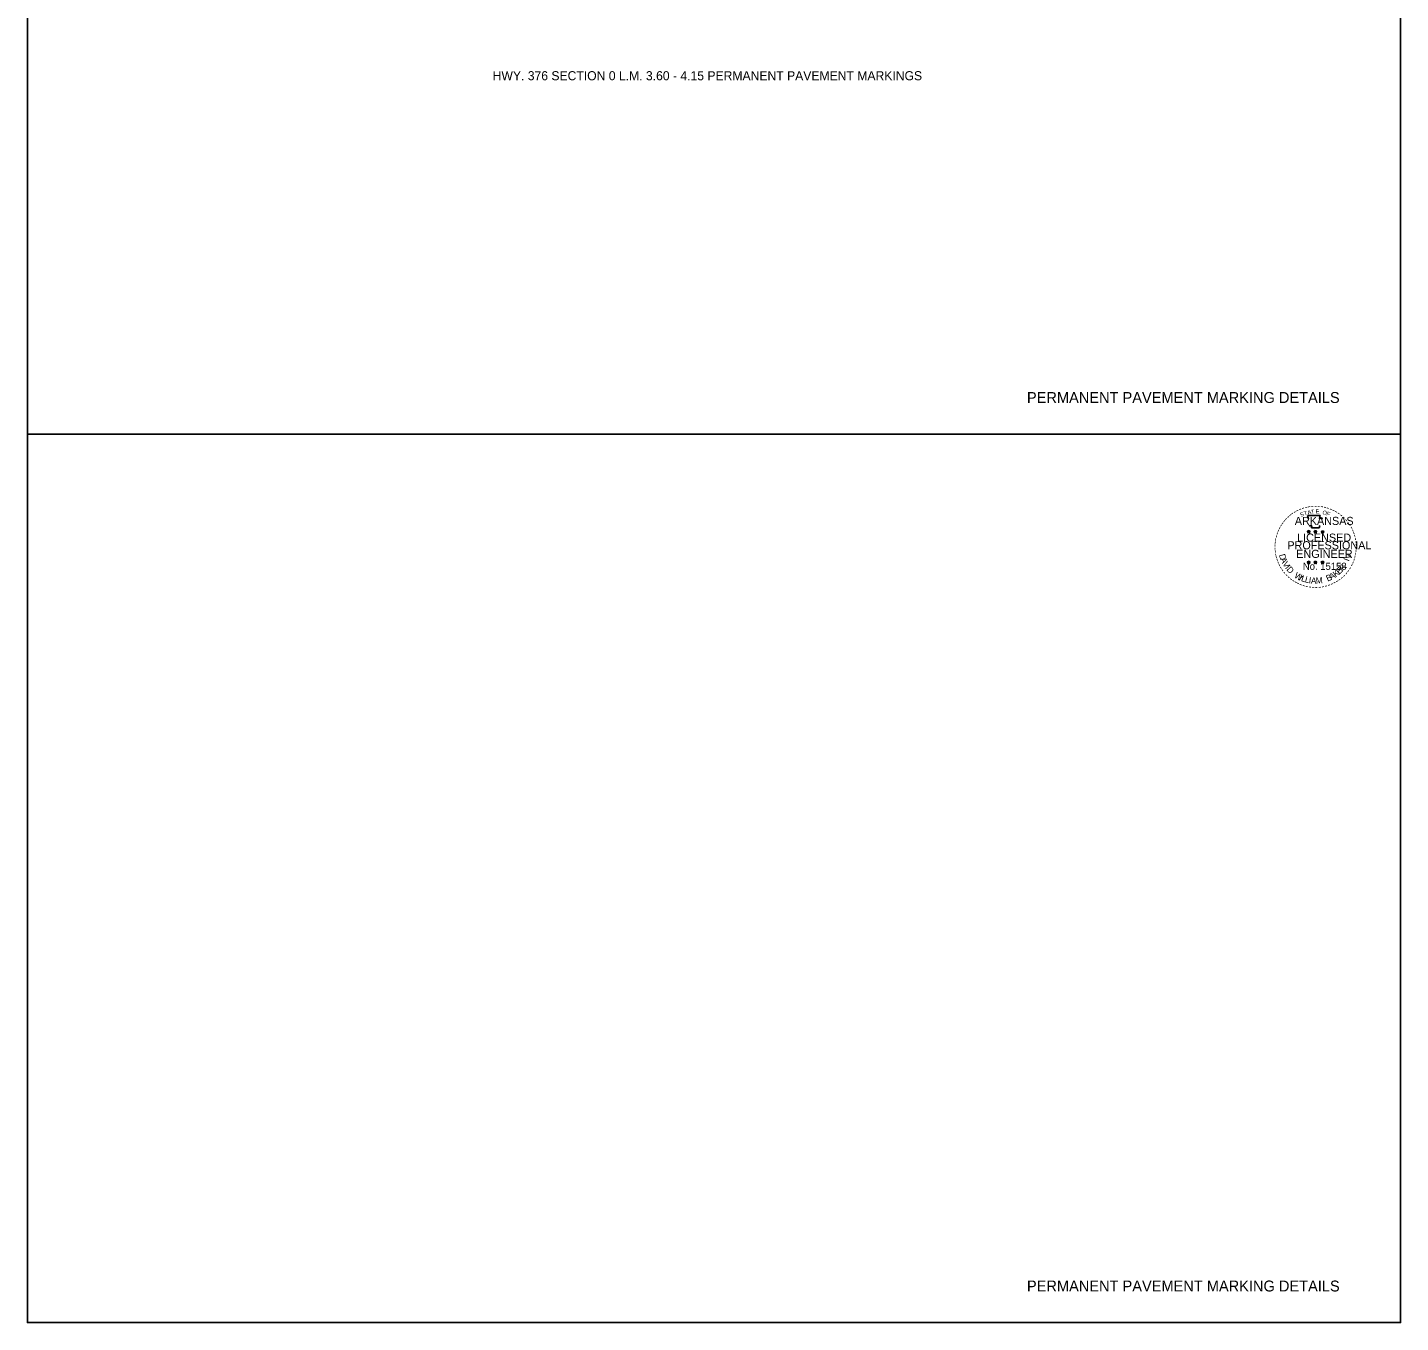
# Model space of a CAD drawing. Extents: x 1372926 to 1373096, y 381240 to 381790.
# Drawn here: x 1372926 to 1373096, y 381240.2 to 381400.5 of the extents above; entities that cross this region are included whole.
import ezdxf

# ---------------------------------------------------------------- set-up
doc = ezdxf.new("R2010")
doc.units = 0
for name, color, linetype in [('Default', 7, 'Continuous'), ('DSN_DRFT_Junk-No-Plot', 7, 'Continuous'), ('R_Border Notes', 7, 'Continuous'), ('R_Draft', 7, 'Continuous'), ('SHET_Border-Text', 7, 'Continuous')]:
    doc.layers.add(name, color=color, linetype=linetype)

msp = doc.modelspace()

# ---------------------------------------------------------------- linework, layer by layer
at = {"layer": 'Default'}
for points in [[(1372925.97, 381460.17), (1372925.97, 381350.17), (1373095.97, 381350.17), (1373095.97, 381460.17)], [(1372925.97, 381350.17), (1372925.97, 381240.17), (1373095.97, 381240.17), (1373095.97, 381350.17)]]:
    msp.add_lwpolyline(points, close=True, dxfattribs=at)
at = {"layer": 'DSN_DRFT_Junk-No-Plot'}
for points in [[(1372925.97, 381460.17), (1373095.97, 381460.17), (1373095.97, 381350.17), (1372925.97, 381350.17)], [(1372925.97, 381460.17), (1372925.97, 381350.17), (1373095.97, 381350.17), (1373095.97, 381460.17)], [(1372925.97, 381350.17), (1373095.97, 381350.17), (1373095.97, 381240.17), (1372925.97, 381240.17)], [(1372925.97, 381350.17), (1372925.97, 381240.17), (1373095.97, 381240.17), (1373095.97, 381350.17)]]:
    msp.add_lwpolyline(points, close=True, dxfattribs=at)
at = {"layer": 'SHET_Border-Text'}
for p, q in [((1373084.43, 381338.13), (1373084.6, 381338.07)), ((1373084.43, 381338.13), (1373084.56, 381338.11)), ((1373084.43, 381338.13), (1373084.55, 381338.07)), ((1373084.5, 381337.93), (1373084.6, 381338.07)), ((1373084.5, 381337.93), (1373084.56, 381338.05)), ((1373084.5, 381337.93), (1373084.6, 381338.03)), ((1373084.6, 381338.26), (1373084.58, 381338.13)), ((1373084.6, 381338.07), (1373084.6, 381338.26)), ((1373084.6, 381338.26), (1373084.63, 381338.13)), ((1373084.78, 381338.13), (1373084.6, 381338.07)), ((1373084.71, 381337.93), (1373084.6, 381338.07)), ((1373084.71, 381337.93), (1373084.6, 381338.03)), ((1373084.78, 381338.13), (1373084.63, 381338.11)), ((1373084.71, 381337.93), (1373084.64, 381338.07)), ((1373084.78, 381338.13), (1373084.67, 381338.08)), ((1373085.26, 381338.13), (1373085.44, 381338.07)), ((1373085.26, 381338.13), (1373085.39, 381338.11)), ((1373085.26, 381338.13), (1373085.38, 381338.07)), ((1373085.33, 381337.93), (1373085.44, 381338.07)), ((1373085.33, 381337.93), (1373085.39, 381338.05)), ((1373085.33, 381337.93), (1373085.44, 381338.03)), ((1373085.44, 381338.26), (1373085.42, 381338.13)), ((1373085.44, 381338.07), (1373085.44, 381338.26)), ((1373085.44, 381338.26), (1373085.46, 381338.13)), ((1373085.61, 381338.13), (1373085.44, 381338.07)), ((1373085.54, 381337.93), (1373085.44, 381338.07)), ((1373085.54, 381337.93), (1373085.44, 381338.03)), ((1373085.61, 381338.13), (1373085.47, 381338.11)), ((1373085.54, 381337.93), (1373085.48, 381338.07)), ((1373085.61, 381338.13), (1373085.51, 381338.08)), ((1373086.15, 381338.12), (1373086.32, 381338.07)), ((1373086.15, 381338.12), (1373086.27, 381338.1)), ((1373086.15, 381338.12), (1373086.26, 381338.06)), ((1373086.21, 381337.92), (1373086.32, 381338.07)), ((1373086.21, 381337.92), (1373086.28, 381338.04)), ((1373086.21, 381337.92), (1373086.32, 381338.03)), ((1373086.32, 381338.25), (1373086.3, 381338.12)), ((1373086.32, 381338.07), (1373086.32, 381338.25)), ((1373086.32, 381338.25), (1373086.34, 381338.13)), ((1373086.49, 381338.12), (1373086.32, 381338.07)), ((1373086.43, 381337.92), (1373086.32, 381338.07)), ((1373086.43, 381337.92), (1373086.32, 381338.03)), ((1373086.49, 381338.12), (1373086.35, 381338.1)), ((1373086.43, 381337.92), (1373086.36, 381338.07)), ((1373086.49, 381338.12), (1373086.39, 381338.07)), ((1373084.43, 381334.34), (1373084.6, 381334.29)), ((1373084.43, 381334.34), (1373084.55, 381334.32)), ((1373084.43, 381334.34), (1373084.55, 381334.28)), ((1373084.49, 381334.14), (1373084.6, 381334.29)), ((1373084.49, 381334.14), (1373084.56, 381334.26)), ((1373084.49, 381334.14), (1373084.6, 381334.25)), ((1373084.6, 381334.47), (1373084.58, 381334.34)), ((1373084.6, 381334.29), (1373084.6, 381334.47)), ((1373084.6, 381334.47), (1373084.63, 381334.35)), ((1373084.77, 381334.34), (1373084.6, 381334.29)), ((1373084.71, 381334.14), (1373084.6, 381334.29)), ((1373084.71, 381334.14), (1373084.6, 381334.25)), ((1373084.77, 381334.34), (1373084.63, 381334.32)), ((1373084.71, 381334.14), (1373084.64, 381334.28)), ((1373084.77, 381334.34), (1373084.67, 381334.29)), ((1373085.26, 381334.34), (1373085.44, 381334.29)), ((1373085.26, 381334.34), (1373085.39, 381334.32)), ((1373085.26, 381334.34), (1373085.38, 381334.28)), ((1373085.33, 381334.14), (1373085.44, 381334.29)), ((1373085.33, 381334.14), (1373085.39, 381334.26)), ((1373085.33, 381334.14), (1373085.43, 381334.25)), ((1373085.44, 381334.47), (1373085.42, 381334.34)), ((1373085.54, 381334.14), (1373085.43, 381334.25)), ((1373085.44, 381334.29), (1373085.44, 381334.47)), ((1373085.44, 381334.47), (1373085.46, 381334.35)), ((1373085.61, 381334.34), (1373085.44, 381334.29)), ((1373085.54, 381334.14), (1373085.44, 381334.29)), ((1373085.61, 381334.34), (1373085.47, 381334.32)), ((1373085.54, 381334.14), (1373085.47, 381334.28)), ((1373085.61, 381334.34), (1373085.51, 381334.29)), ((1373086.14, 381334.34), (1373086.32, 381334.28)), ((1373086.14, 381334.34), (1373086.27, 381334.32)), ((1373086.14, 381334.34), (1373086.26, 381334.28)), ((1373086.21, 381334.13), (1373086.32, 381334.28)), ((1373086.21, 381334.13), (1373086.27, 381334.26)), ((1373086.21, 381334.13), (1373086.32, 381334.24)), ((1373086.32, 381334.47), (1373086.3, 381334.34)), ((1373086.32, 381334.28), (1373086.32, 381334.47)), ((1373086.32, 381334.47), (1373086.34, 381334.34)), ((1373086.49, 381334.34), (1373086.32, 381334.28)), ((1373086.43, 381334.13), (1373086.32, 381334.28)), ((1373086.43, 381334.13), (1373086.32, 381334.24)), ((1373086.49, 381334.34), (1373086.35, 381334.31)), ((1373086.43, 381334.13), (1373086.36, 381334.28)), ((1373086.49, 381334.34), (1373086.39, 381334.29))]:
    msp.add_line(p, q, dxfattribs=at)
for points in [[(1373084.45, 381340.07), (1373084.58, 381339.66)], [(1373086.2, 381339.61), (1373086.28, 381339.75), (1373085.93, 381339.74), (1373086.01, 381340.07), (1373084.45, 381340.07)], [(1373084.6, 381338.26), (1373084.71, 381337.93), (1373084.43, 381338.13), (1373084.78, 381338.13), (1373084.5, 381337.93), (1373084.6, 381338.26)], [(1373084.7, 381338.86), (1373084.7, 381338.81), (1373084.98, 381338.8), (1373084.95, 381338.57), (1373085.88, 381338.57), (1373085.99, 381338.84)], [(1373085.44, 381338.26), (1373085.54, 381337.93), (1373085.26, 381338.13), (1373085.61, 381338.13), (1373085.33, 381337.93), (1373085.44, 381338.26)], [(1373086.32, 381338.25), (1373086.43, 381337.92), (1373086.15, 381338.12), (1373086.49, 381338.12), (1373086.21, 381337.92), (1373086.32, 381338.25)], [(1373084.6, 381334.47), (1373084.71, 381334.14), (1373084.43, 381334.34), (1373084.77, 381334.34), (1373084.49, 381334.14), (1373084.6, 381334.47)], [(1373085.44, 381334.47), (1373085.54, 381334.14), (1373085.26, 381334.34), (1373085.61, 381334.34), (1373085.33, 381334.14), (1373085.44, 381334.47)], [(1373086.32, 381334.47), (1373086.43, 381334.13), (1373086.14, 381334.34), (1373086.49, 381334.34), (1373086.21, 381334.13), (1373086.32, 381334.47)]]:
    msp.add_lwpolyline(points, dxfattribs=at)
for centre, radius in [((1373084.6, 381338.07), 0.0861), ((1373084.6, 381338.07), 0.0723), ((1373084.6, 381338.07), 0.0579), ((1373084.6, 381338.07), 0.0495), ((1373084.6, 381338.07), 0.0374), ((1373084.6, 381338.07), 0.0248), ((1373084.6, 381338.07), 0.0148), ((1373085.44, 381338.07), 0.0861), ((1373085.44, 381338.07), 0.0723), ((1373085.44, 381338.07), 0.0579), ((1373085.44, 381338.07), 0.0495), ((1373085.44, 381338.07), 0.0374), ((1373085.44, 381338.07), 0.0248), ((1373085.44, 381338.07), 0.0148), ((1373086.32, 381338.07), 0.0861), ((1373086.32, 381338.07), 0.0723), ((1373086.32, 381338.07), 0.0579), ((1373086.32, 381338.07), 0.0495), ((1373086.32, 381338.07), 0.0374), ((1373086.32, 381338.07), 0.0248), ((1373086.32, 381338.07), 0.0148), ((1373084.6, 381334.29), 0.0861), ((1373084.6, 381334.29), 0.0723), ((1373084.6, 381334.29), 0.0579), ((1373084.6, 381334.29), 0.0495), ((1373084.6, 381334.29), 0.0374), ((1373084.6, 381334.29), 0.0248), ((1373084.6, 381334.29), 0.0148), ((1373085.44, 381334.29), 0.0861), ((1373085.44, 381334.29), 0.0723), ((1373085.44, 381334.29), 0.0579), ((1373085.44, 381334.29), 0.0495), ((1373085.44, 381334.29), 0.0374), ((1373085.44, 381334.29), 0.0248), ((1373085.44, 381334.29), 0.0148), ((1373086.32, 381334.28), 0.0861), ((1373086.32, 381334.28), 0.0723), ((1373086.32, 381334.28), 0.0579), ((1373086.32, 381334.28), 0.0495), ((1373086.32, 381334.28), 0.0374), ((1373086.32, 381334.28), 0.0248), ((1373086.32, 381334.28), 0.0148)]:
    msp.add_circle(centre, radius, dxfattribs=at)

# ---------------------------------------------------------------- texts
at = {"layer": 'R_Border Notes'}
for p in [(1373049.72, 381354.02), (1373049.72, 381244.02)]:
    msp.add_text('PERMANENT PAVEMENT MARKING DETAILS', height=1.35, dxfattribs=at).set_placement(p)
at = {"layer": 'R_Draft'}
msp.add_text('HWY. 376 SECTION 0 L.M. 3.60 - 4.15 PERMANENT PAVEMENT MARKINGS', height=1.125, dxfattribs=at).set_placement((1372983.57, 381393.97))
at = {"layer": 'SHET_Border-Text'}
for s, height, rotation, p in [('-', 0.8, 34.0636, (1373082.89, 381340.15)), ('-', 0.8, 28.7918, (1373083.19, 381340.34)), ('-', 0.8, 24.3072, (1373083.51, 381340.5)), ('-', 0.8, 19.1761, (1373083.82, 381340.63)), ('T', 0.5, 16.4036, (1373084.08, 381340.07)), ('-', 0.8, 13.6302, (1373084.2, 381340.75)), ('A', 0.5, 11.2132, (1373084.5, 381340.2)), ('-', 0.8, 10.2193, (1373084.54, 381340.83)), ('T', 0.5, 6.0228, (1373084.92, 381340.28)), ('-', 0.8, 5.8968, (1373084.9, 381340.89)), ('-', 0.8, 0.1862, (1373085.29, 381340.92)), ('E', 0.5, 0.8323, (1373085.47, 381340.34)), ('-', 0.8, 357.743, (1373085.65, 381340.92)), ('-', 0.8, 352.1617, (1373086.02, 381340.89)), ('O', 0.5, 350.4515, (1373086.28, 381340.23)), ('-', 0.8, 347.2049, (1373086.38, 381340.83)), ('-', 0.8, 342.3362, (1373086.7, 381340.76)), ('-', 0.8, 337.8551, (1373087.07, 381340.64)), ('-', 0.8, 334.1211, (1373087.38, 381340.51)), ('-', 0.8, 329.6409, (1373087.67, 381340.37)), ('-', 0.8, 58.0706, (1373081.35, 381338.53)), ('-', 0.8, 54.2325, (1373081.52, 381338.79)), ('-', 0.8, 50.6142, (1373081.72, 381339.08)), ('-', 0.8, 48.4231, (1373081.92, 381339.32)), ('-', 0.8, 42.9622, (1373082.15, 381339.56)), ('-', 0.8, 38.9507, (1373082.36, 381339.77)), ('-', 0.8, 36.2317, (1373082.6, 381339.96)), ('S', 0.5, 21.594, (1373083.63, 381339.91)), ('F', 0.5, 340.0707, (1373086.75, 381340.12)), ('-', 0.8, 325.8627, (1373087.99, 381340.19)), ('-', 0.8, 320.5297, (1373088.3, 381339.97)), ('-', 0.8, 315.5786, (1373088.6, 381339.73)), ('-', 0.8, 309.8797, (1373088.88, 381339.45)), ('-', 0.8, 306.6522, (1373089.14, 381339.15)), ('-', 0.7, 303.6753, (1373089.39, 381338.87)), ('-', 0.8, 81.2013, (1373080.79, 381336.89)), ('-', 0.8, 75.461, (1373080.86, 381337.25)), ('-', 0.8, 72.3945, (1373080.96, 381337.6)), ('-', 0.8, 67.7743, (1373081.07, 381337.92)), ('-', 0.8, 62.8713, (1373081.2, 381338.22)), ('-', 0.8, 299.6684, (1373089.55, 381338.57)), ('-', 0.8, 294.6628, (1373089.71, 381338.26)), ('-', 0.8, 290.5728, (1373089.84, 381337.97)), ('-', 0.8, 285.1233, (1373089.95, 381337.68)), ('-', 0.8, 280.5493, (1373090.05, 381337.31)), ('-', 0.8, 94.1959, (1373080.76, 381335.83)), ('-', 0.8, 89.0622, (1373080.74, 381336.19)), ('-', 0.8, 98.9479, (1373080.8, 381335.5)), ('-', 0.8, 85.1863, (1373080.75, 381336.54)), ('V', 0.77, 72.6573, (1373089.7, 381334.62)), ('-', 0.8, 260.9953, (1373090.14, 381335.59)), ('-', 0.8, 276.5962, (1373090.13, 381336.93)), ('-', 0.8, 263.5172, (1373090.17, 381335.92)), ('-', 0.8, 274.3301, (1373090.16, 381336.57)), ('-', 0.8, 269.9407, (1373090.18, 381336.25)), ('-', 0.8, 101.7149, (1373080.86, 381335.13)), ('-', 0.8, 105.4578, (1373080.94, 381334.83)), ('-', 0.8, 109.0874, (1373081.05, 381334.52)), ('-', 0.8, 114.0643, (1373081.18, 381334.22)), ('-', 0.8, 115.7289, (1373081.33, 381333.91)), ('D', 0.77, 286.2848, (1373080.91, 381335.2)), ('A', 0.77, 292.7835, (1373081.05, 381334.7)), ('V', 0.77, 300.7936, (1373081.31, 381334.11)), ('I', 0.77, 308.3502, (1373081.63, 381333.59)), ('D', 0.77, 311.9774, (1373081.8, 381333.36)), ('R', 0.77, 50.3651, (1373088.77, 381333.11)), ('I', 0.77, 69.0301, (1373089.59, 381334.35)), ('-', 0.8, 244.6197, (1373089.75, 381334.24)), ('-', 0.8, 247.8887, (1373089.88, 381334.55)), ('-', 0.8, 252.8681, (1373089.99, 381334.89)), ('-', 0.8, 255.7626, (1373090.08, 381335.25)), ('-', 0.8, 120.4471, (1373081.51, 381333.62)), ('-', 0.8, 125.8934, (1373081.71, 381333.34)), ('-', 0.8, 130.7181, (1373081.94, 381333.06)), ('-', 0.8, 134.2238, (1373082.2, 381332.79)), ('-', 0.8, 138.9338, (1373082.46, 381332.56)), ('-', 0.8, 144.6463, (1373082.74, 381332.35)), ('-', 0.8, 148.0898, (1373083.02, 381332.17)), ('W', 0.77, 328.0731, (1373082.74, 381332.47)), ('I', 0.77, 336.6877, (1373083.33, 381332.12)), ('L', 0.77, 340.3149, (1373083.6, 381332)), ('L', 0.77, 346.6625, (1373084.08, 381331.83)), ('I', 0.77, 353.0101, (1373084.58, 381331.71)), ('A', 0.77, 356.6373, (1373084.86, 381331.66)), ('M', 0.77, 4.6473, (1373085.51, 381331.64)), ('B', 0.77, 22.8589, (1373086.94, 381331.9)), ('A', 0.77, 28.9042, (1373087.39, 381332.09)), ('K', 0.77, 36.9143, (1373087.95, 381332.41)), ('E', 0.77, 44.0175, (1373088.4, 381332.75)), ('-', 0.8, 215.7363, (1373088.36, 381332.48)), ('-', 0.8, 221.0851, (1373088.63, 381332.72)), ('-', 0.8, 225.7653, (1373088.9, 381332.97)), (',', 0.77, 57.4684, (1373089.13, 381333.55)), ('-', 0.8, 231.2538, (1373089.14, 381333.25)), ('-', 0.8, 233.8452, (1373089.35, 381333.54)), ('-', 0.8, 239.0712, (1373089.55, 381333.86)), ('-', 0.8, 151.5704, (1373083.31, 381332.01)), ('-', 0.8, 154.6002, (1373083.57, 381331.88)), ('-', 0.8, 158.5612, (1373083.88, 381331.76)), ('-', 0.8, 162.7983, (1373084.23, 381331.65)), ('-', 0.8, 167.5555, (1373084.59, 381331.57)), ('-', 0.8, 173.1155, (1373084.97, 381331.51)), ('-', 0.8, 176.5183, (1373085.35, 381331.49)), ('-', 0.8, 181.5918, (1373085.72, 381331.49)), ('-', 0.8, 185.8167, (1373086.12, 381331.53)), ('-', 0.8, 191.2858, (1373086.49, 381331.6)), ('-', 0.8, 195.4743, (1373086.85, 381331.7)), ('-', 0.8, 199.4643, (1373087.19, 381331.82)), ('-', 0.8, 204.2516, (1373087.5, 381331.96)), ('-', 0.8, 207.3568, (1373087.81, 381332.12)), ('-', 0.8, 212.2491, (1373088.09, 381332.29))]:
    msp.add_text(s, height=height, rotation=rotation, dxfattribs=at).set_placement(p)
for s, height, p in [('ARKANSAS', 1, (1373082.88, 381338.92)), ('LICENSED', 1, (1373083.17, 381336.85)), ('PROFESSIONAL', 1, (1373081.96, 381335.9)), ('ENGINEER', 1, (1373083.06, 381334.84)), ('No. 15158', 0.878, (1373083.88, 381333.36)), ('AAMU', 0.00001, (1373085.4, 381331.63))]:
    msp.add_text(s, height=height, dxfattribs=at).set_placement(p)

doc.saveas('drawing.dxf')
